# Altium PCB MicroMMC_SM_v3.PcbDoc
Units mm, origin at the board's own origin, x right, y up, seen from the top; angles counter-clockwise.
Board outline 50 x 25 mm, 4 copper layers (Top Layer, GND1, GND2, Bottom Layer), stack 1.586 mm thick; 71 components, 41 nets, 213 pads, 184 vias.
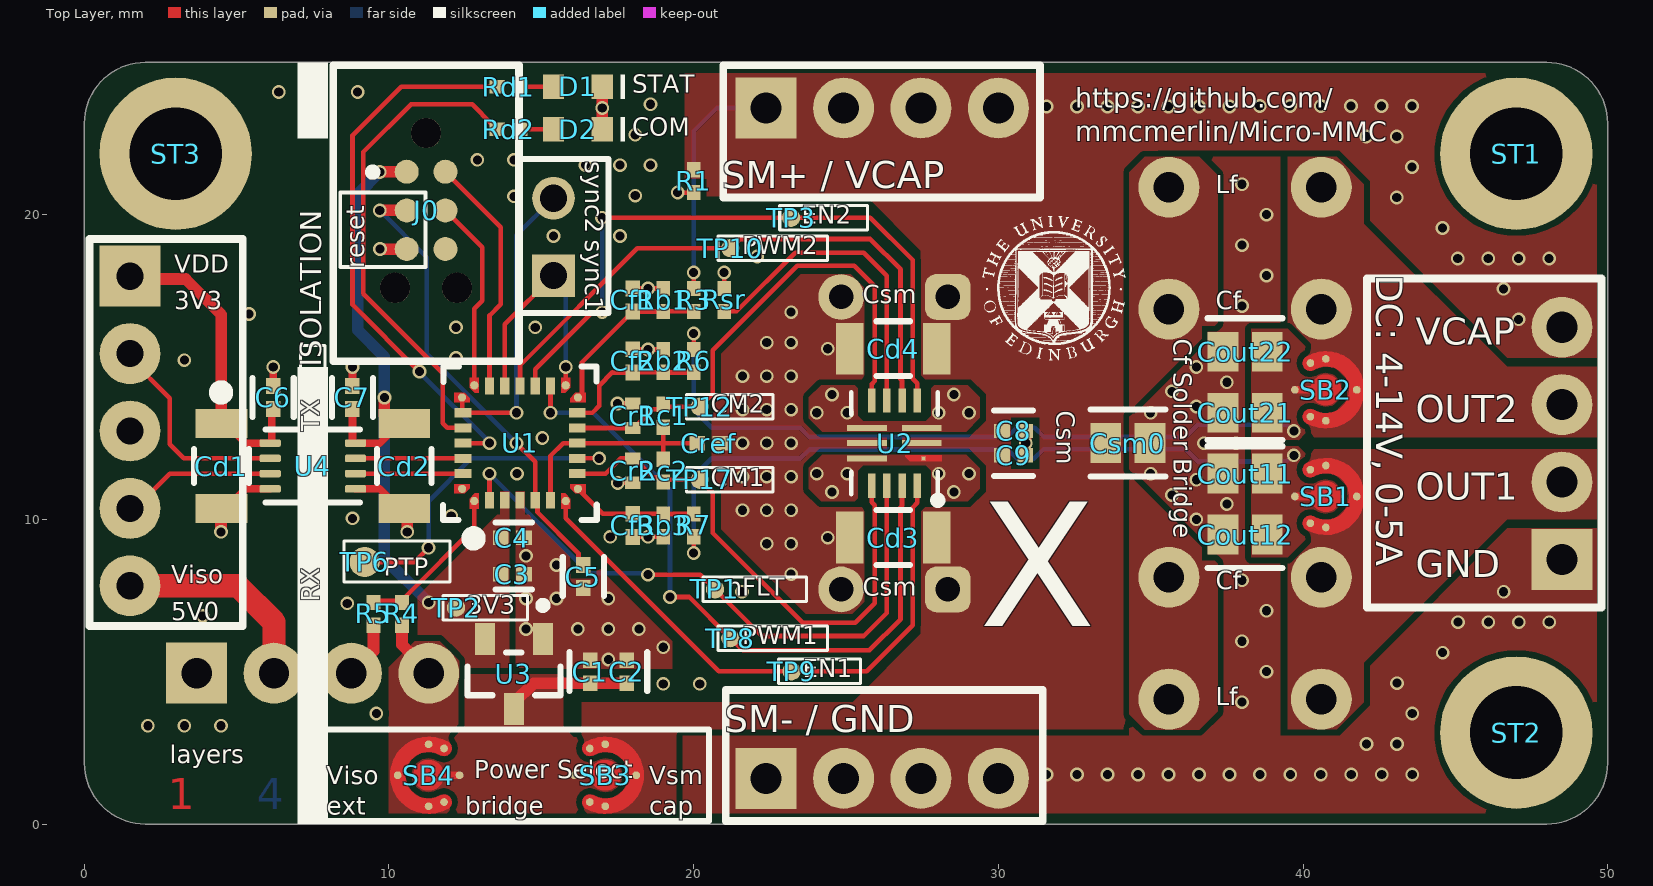
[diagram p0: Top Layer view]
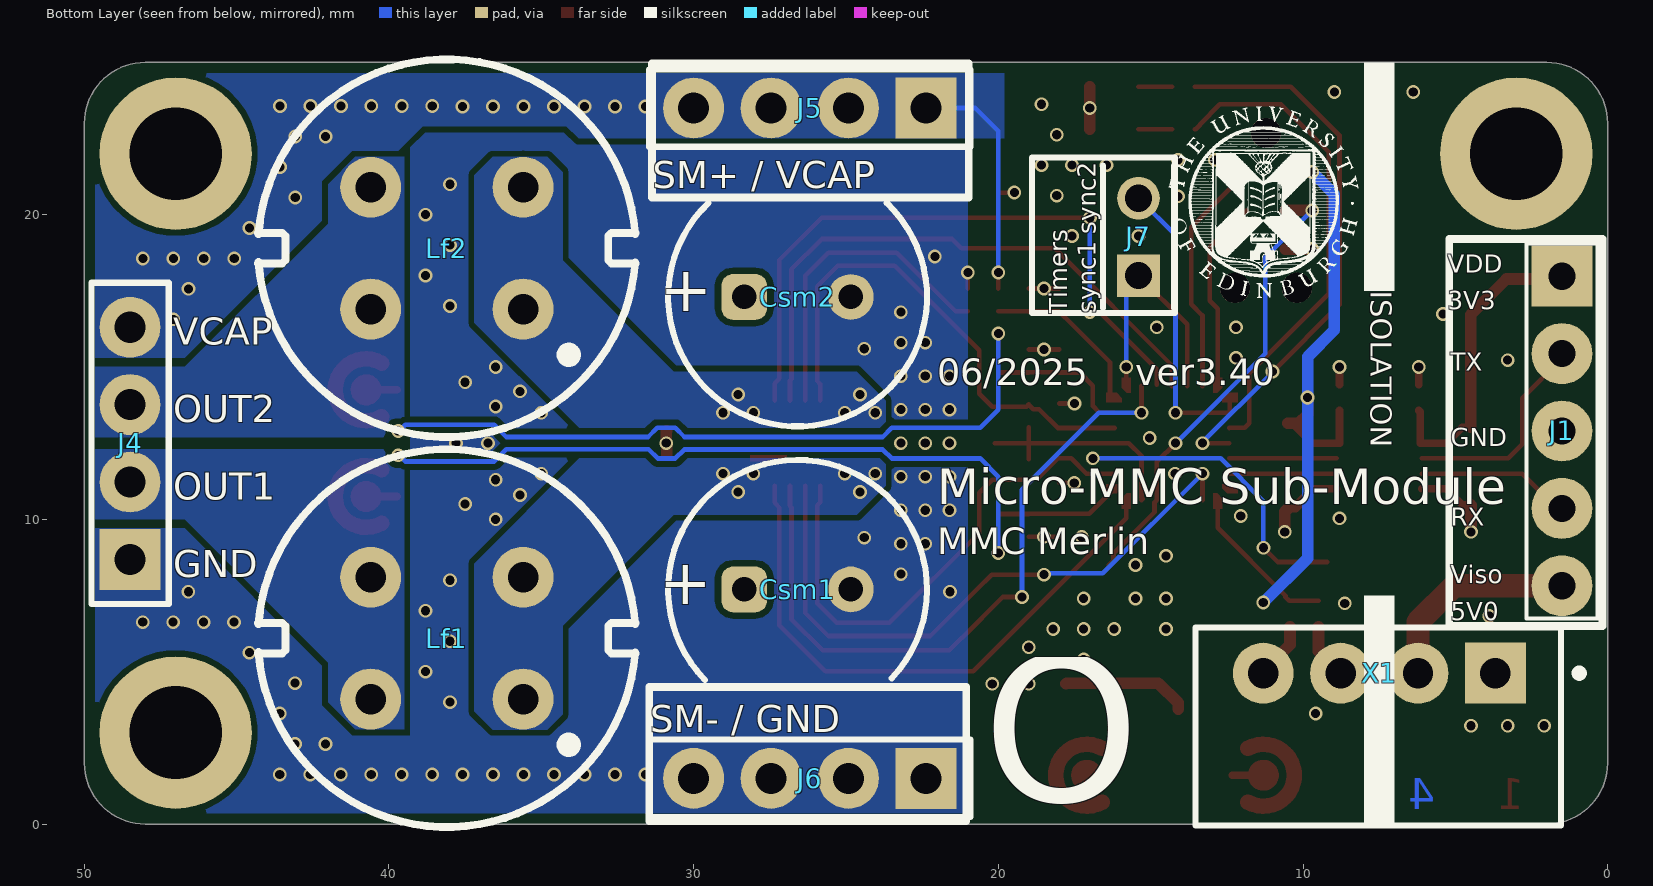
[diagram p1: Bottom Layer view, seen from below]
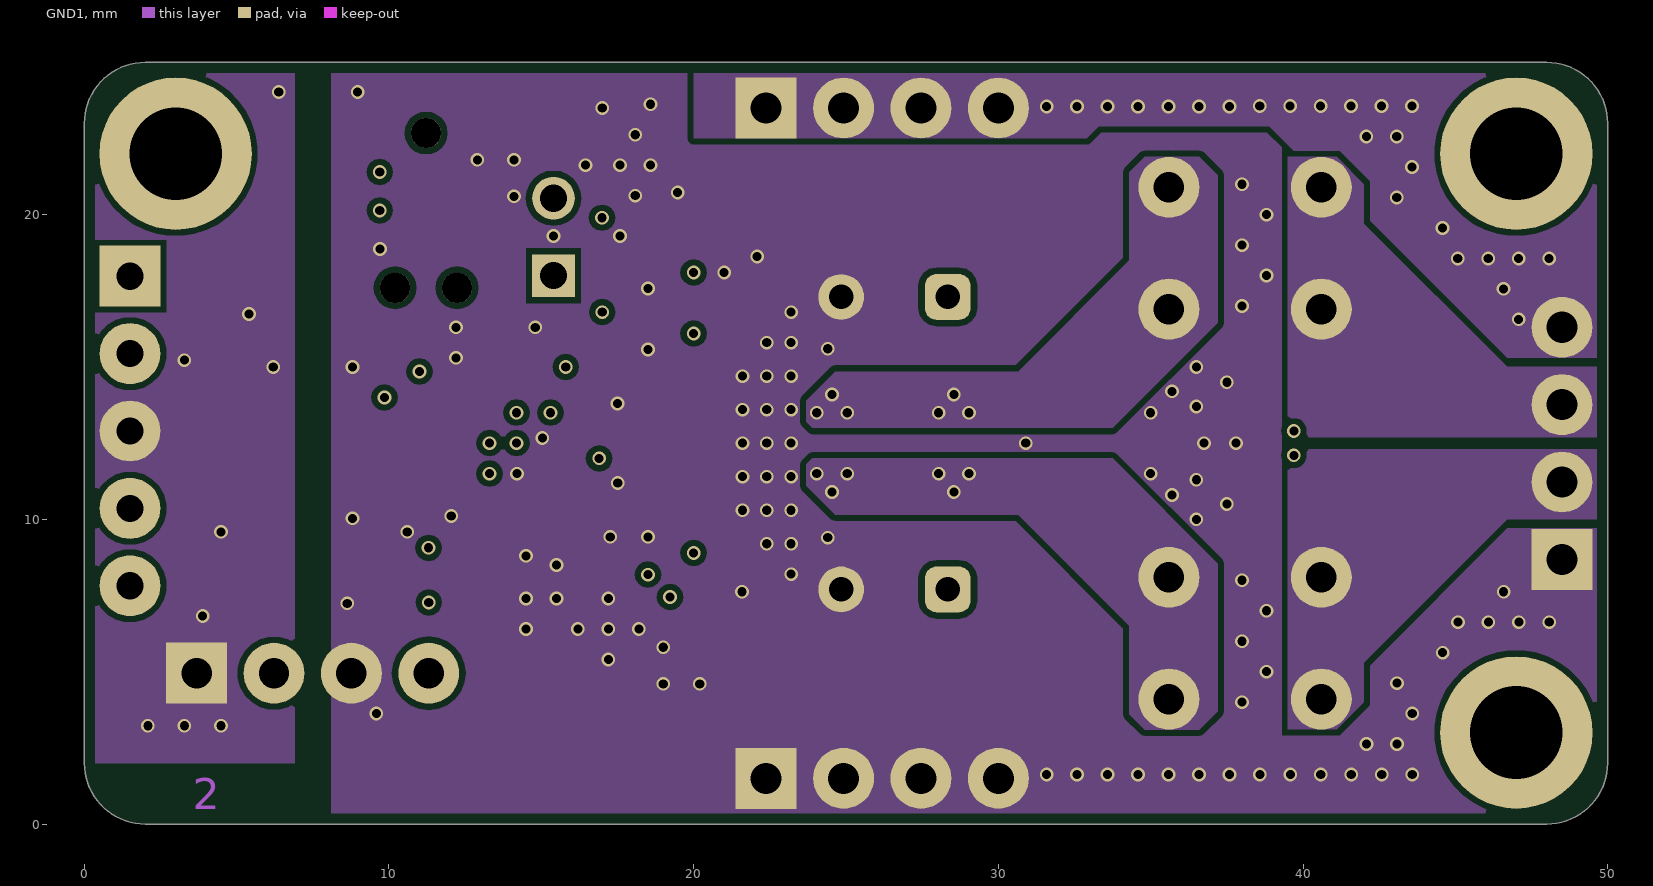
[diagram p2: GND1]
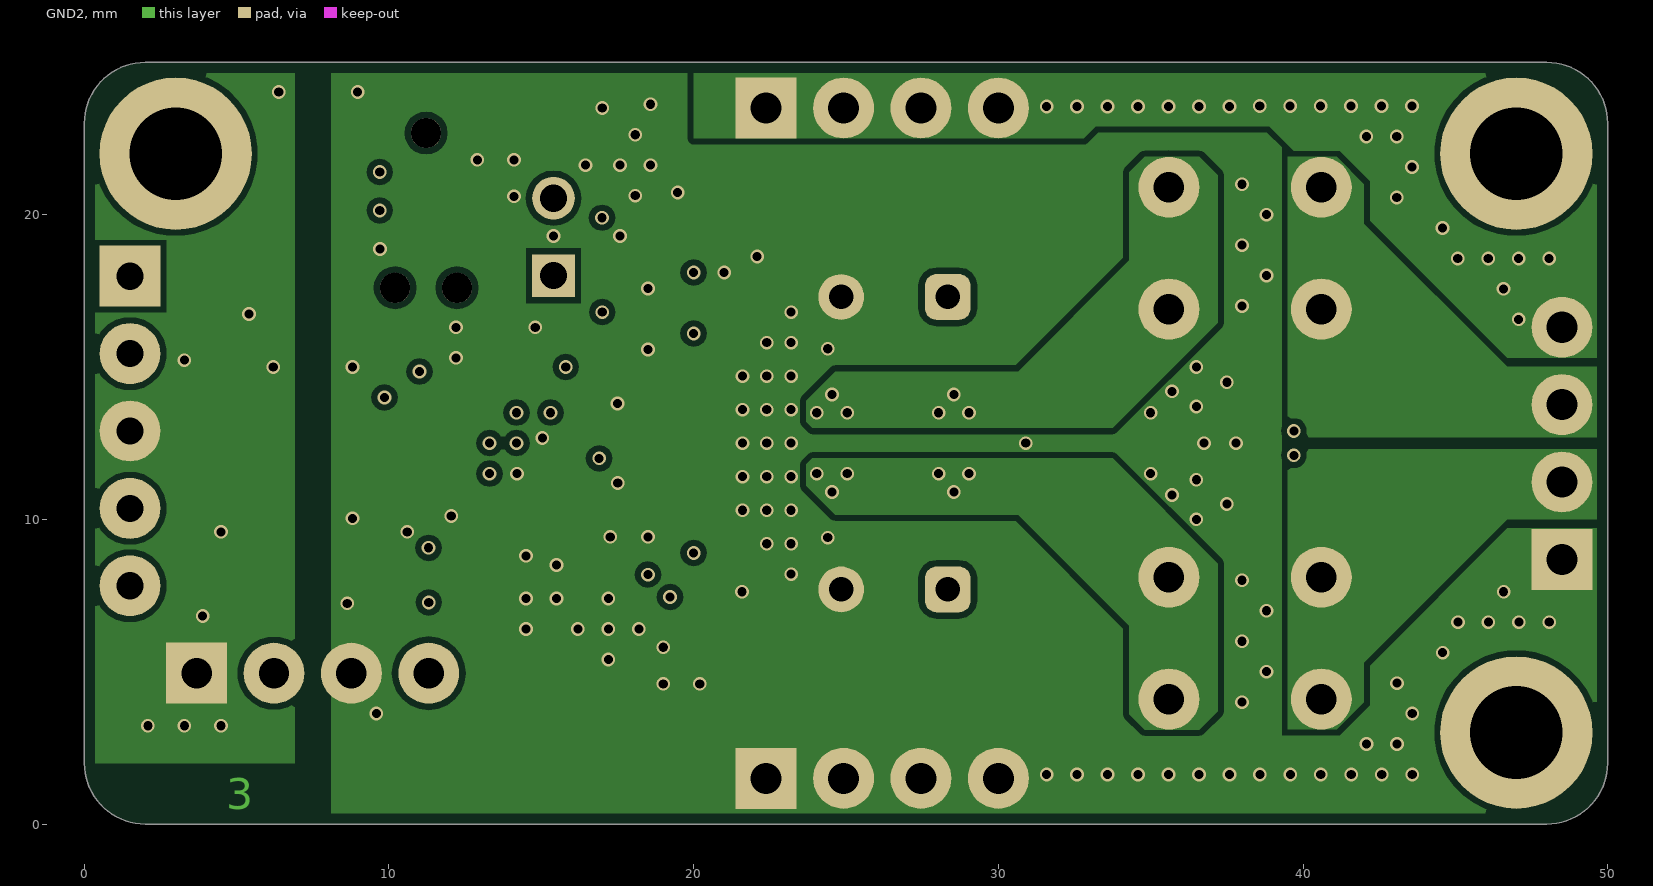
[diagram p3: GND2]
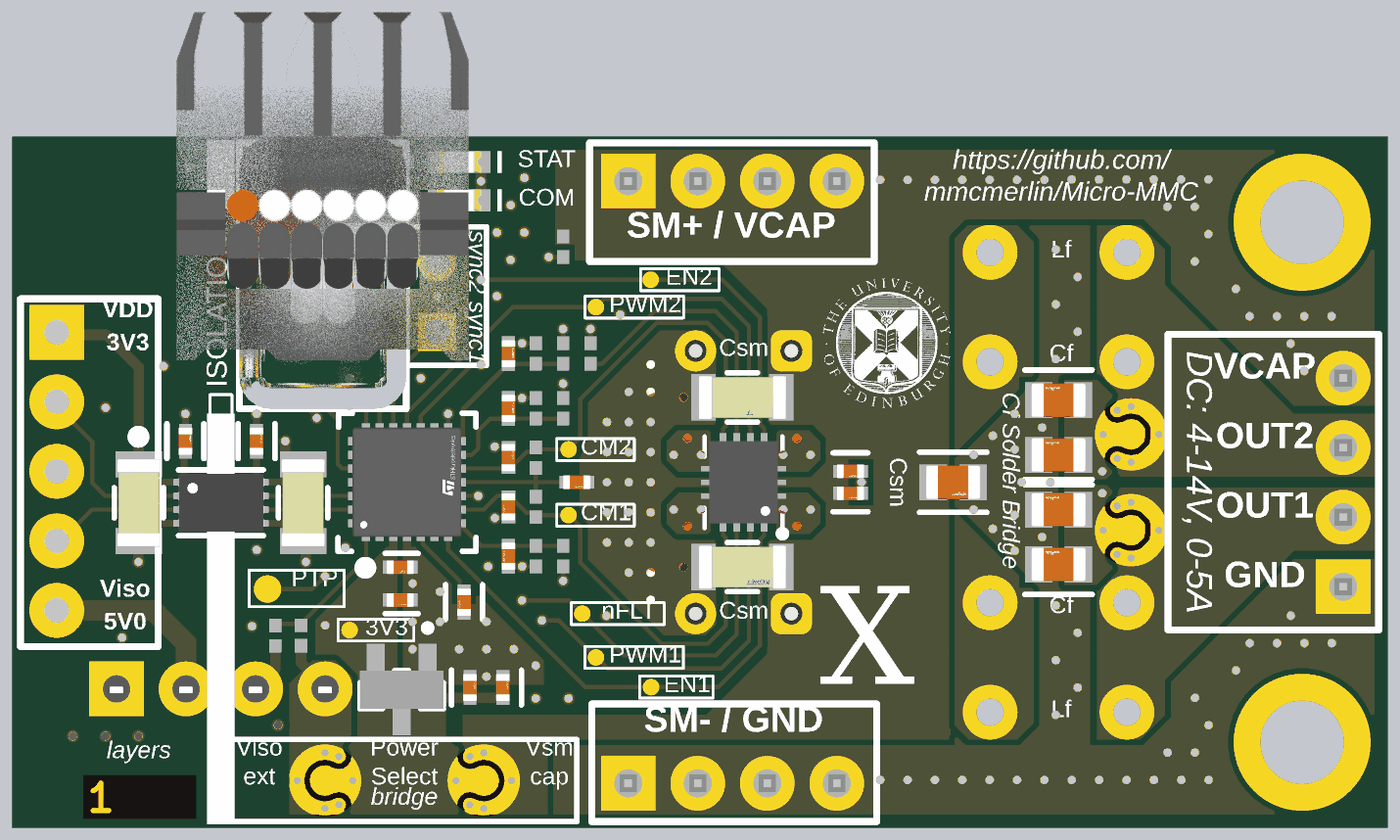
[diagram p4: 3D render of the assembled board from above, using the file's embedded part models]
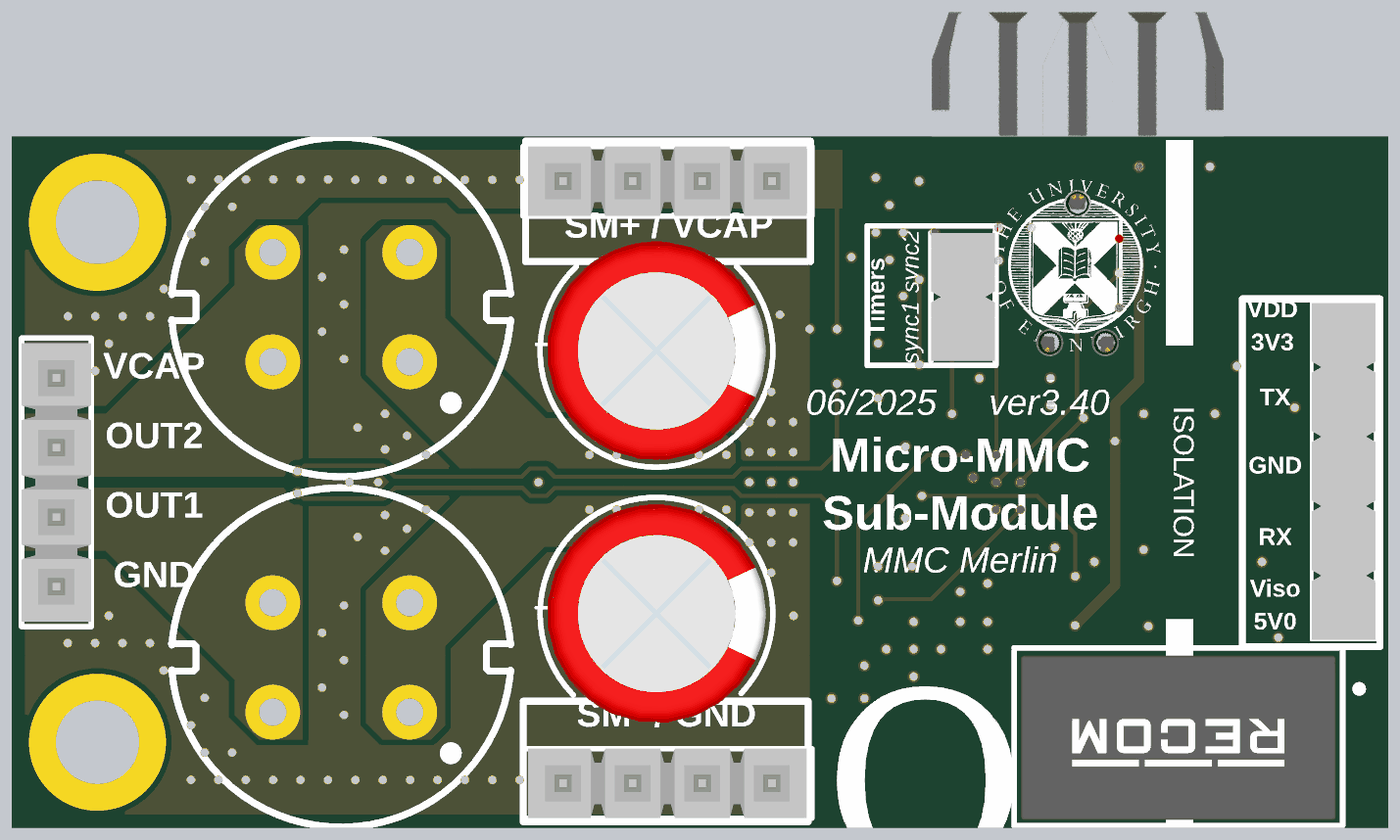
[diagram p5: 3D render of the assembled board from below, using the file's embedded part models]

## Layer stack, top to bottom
Top Solder: solder mask 0.0127, Solder Resist, Dk 3.8
Top Layer: signal copper 0.035
Dielectric 1: prepreg 0.2104, PP-022, Dk 4.6
GND1: signal copper 0.0152
Dielectric1: core 1.065, FR-4, Dk 4.6
GND2: signal copper 0.0152
Dielectric 2: prepreg 0.2104, PP-022, Dk 4.6
Bottom Layer: signal copper 0.035
Bottom Solder: solder mask 0.0127, Solder Resist, Dk 3.8

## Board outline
0,2 0,23 cw(c2,23) 2,25 48,25 cw(c48,23) 50,23 50,2 cw(c48,2) 48,0 2,0 cw(c2,2)

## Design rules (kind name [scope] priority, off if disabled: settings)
BoardOutlineClearance [All] p1: gap=0.35 ignorepadtopadclearanceinfootprint=FALSE
Clearance [All] p1: gap=0.2 ignorepadtopadclearanceinfootprint=FALSE except(0.254: Via-Via)
Height [All] p1: minheight=0 maxheight=100 prefheight=12.7
HoleSize [All] p1: absolutevalues=TRUE maxlimit=6 minlimit=0.25 maxpercent=80.000 minpercent=20.000
HoleToHoleClearance [All] p1: gap=0.45 allowstackedmicrovias=TRUE
MinimumSolderMaskSliver [All] p1: minsoldermaskwidth=0.1
PlaneConnect [All] p1: planeconnectstyle=Direct reliefexpansion=0.508 reliefentries=4 reliefconductorwidth=0.254 reliefairgap=0.254
PolygonConnect [All] p1: connectstyle=Direct reliefconductorwidth=0.254 reliefentries=4 polygonreliefangle="90 Angle" airgapwidth=0.254
RoutingVias [All] p1: holewidth=1 width=2 viastyle="Through Hole" minholewidth=0.3 minwidth=0.45 maxholewidth=6 maxwidth=12
SilkToSolderMaskClearance [IsPad] p1: minsilkscreentomaskgap=0.15 clearancetoexposedcopper=TRUE
SolderMaskExpansion [Not IsVia] p1: expansion=0.04 istentingtop=FALSE
SolderMaskExpansion SolderMaskExpansion_via [IsVia] p2: expansion=0.102 istentingtop=TRUE
SupplyNets "Schematic Supply Nets_5" [InNet('GND_SM')] p1: voltage=0.000
SupplyNets "Schematic Supply Nets_7" [InNet('Viso_SM')] p2: voltage=0.000
SupplyNets "Schematic Supply Nets_6" [InNet('+3.3V_SM')] p3: voltage=0.000
SupplyNets "Schematic Supply Nets_4" [InNet('Vdd_MA')] p4: voltage=0.000
SupplyNets "Schematic Supply Nets_3" [InNet('GND_MA')] p5: voltage=0.000
SupplyNets "Schematic Supply Nets_2" [InNet('V_REF')] p6: voltage=0.000
SupplyNets "Schematic Supply Nets_1" [InNet('Viso_MA')] p7: voltage=0.000
SupplyNets "Schematic Supply Nets" [InNet('VCAP_SM')] p8: voltage=0.000
UnRoutedNet [All] p1: checkbadconnections=TRUE
Width [All] p1: maxlimit=0.762 minlimit=0.152 preferedwidth=0.381
23 further rules are at their usual default settings.

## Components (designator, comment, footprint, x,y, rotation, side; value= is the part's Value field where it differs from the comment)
C1 "GRM155R61E105KA12D" FP-GRM155-0_05-IPC_C 16.6,5 r90 top
C2 "GRM155R61E105KA12D" FP-GRM155-0_05-IPC_C 17.8,5 r90 top
C3 "GRM155R61E105KA12D" FP-GRM155-0_05-IPC_C 14.05,8.2 r0 top
C4 "GRM155R61E105KA12D" FP-GRM155-0_05-IPC_C 14.05,9.4 r0 top
C5 "GRM155R61E105KA12D" FP-GRM155-0_05-IPC_C 16.379,8.121 r270 top
C6 "GRM155R61E105KA12D" FP-GRM155-0_05-IPC_C 6.2,14 r90 top
C7 "GRM155R61E105KA12D" FP-GRM155-0_05-IPC_C 8.8,14 r90 top
C8 "GRM155R61E105KA12D" FP-GRM155-0_05-IPC_C 30.5,12.9 r0 top
C9 "GRM155R61E105KA12D" FP-GRM155-0_05-IPC_C 30.5,12.1 r0 top
Cd1 "C1206C104M5RACTU" FP-C1206C-EB-MFG#1 4.5,11.75 r270 top value="0.10 μF"
Cd2 "C1206C104M5RACTU" FP-C1206C-EB-MFG#1 10.5,11.75 r270 top value="0.10 μF"
Cd3 "C1206C104M5RACTU" FP-C1206C-EB-MFG#2 26.55,9.4 r180 top value="0.10 μF"
Cd4 "C1206C104M5RACTU" FP-C1206C-EB-MFG#2 26.55,15.6 r180 top value="0.10 μF"
Cf1 "CL05B103KB5NNNC" FP-CL165-IPC_C 18,17.2 r90 top
Cf2 "CL05B103KB5NNNC" FP-CL165-IPC_C 18,15.2 r90 top
Cf3 "CL05B103KB5NNNC" FP-CL165-IPC_C 18,9.8 r270 top
Cout11 "GRM21BR61H475ME51L" FP-GRM21B-0_15-IPC_C 38.1,11.5 r180 top
Cout12 "GRM21BR61H475ME51L" FP-GRM21B-0_15-IPC_C 38.1,9.5 r180 top
Cout21 "GRM21BR61H475ME51L" FP-GRM21B-0_15-IPC_C 38.1,13.5 r180 top
Cout22 "GRM21BR61H475ME51L" FP-GRM21B-0_15-IPC_C 38.1,15.5 r180 top
Cr1 "GJM1555C1H100JB01D" FP-GJM155-0_05-MFG 18,13.4 r90 top
Cr2 "GJM1555C1H100JB01D" FP-GJM155-0_05-MFG 18,11.6 r270 top
Cref "GRM155R61E105KA12D" FP-GRM155-0_05-IPC_C 20.5,12.5 r0 top
Csm0 "GRM21BR61H475ME51L" FP-GRM21B-0_15-IPC_C 34.25,12.5 r0 top
Csm1 "860010474012" WCAP-ATG8_D8H11.5 26.59,7.7 r0 bottom value=470uF
Csm2 "860010474012" WCAP-ATG8_D8H11.5 26.59,17.3 r0 bottom value=470uF
D1 "150060RS75000" WL-SMCW_0603_150060xx75000 16.2,24.2 r180 top
D2 "150060RS75000" WL-SMCW_0603_150060xx75000 16.2,22.8 r180 top
J0 "TC2030-CTX-NL" FP-TC2030-CTX-NL-MFG 11.216,20.14 r270 top
J1 "5-146280-5" 5-146280-5 1.5,17.98 r270 bottom
J4 "TSW-104-08-L-S" SMTC-TSW-104-08-X-S 48.5,8.685 r90 bottom
J5 "TSW-104-08-L-S" SMTC-TSW-104-08-X-S 22.38,23.5 r0 bottom
J6 "TSW-104-08-L-S" SMTC-TSW-104-08-X-S 22.38,1.5 r0 bottom
J7 "5-146280-2" TECO-5-146280-2_V 15.4,19.27 r90 bottom
Lf1 "RCH1216BNP-100M" "TH Inductor" 35.6,8.1 r270 bottom
Lf2 "RCH1216BNP-100M" "TH Inductor" 35.6,20.9 r270 bottom
R1 "RC0402FR-0710KL" RESC1005X40X25LL05T10 20,21.1 r90 top
R3 "RC0402FR-0710KL" RESC1005X40X25LL05T10 20,17.2 r90 top
R4 "RC0402FR-0710KL" RESC1005X40X25LL05T10 10.426,6.897 r270 top
R5 "RC0402FR-0710KL" RESC1005X40X25LL05T10 9.491,6.896 r90 top
R6 "RC0402FR-0710KL" RESC1005X40X25LL05T10 20,15.2 r90 top
R7 "RC0402FR-0710KL" RESC1005X40X25LL05T10 20,9.8 r270 top
Rb1 "RC0402FR-073K3L" RESC1005X40X25LL05T10 19,17.2 r270 top
Rb2 "RC0402FR-073K3L" RESC1005X40X25LL05T10 19,15.2 r270 top
Rb3 "RC0402FR-073K3L" RESC1005X40X25LL05T10 19,9.8 r90 top
Rc1 "RC0402FR-073K3L" RESC1005X40X25LL05T10 19,13.4 r270 top
Rc2 "RC0402FR-073K3L" RESC1005X40X25LL05T10 19,11.6 r90 top
Rd1 "RC0402FR-073K3L" RESC1005X40X25LL05T10 13.925,24.2 r0 top
Rd2 "RC0402FR-073K3L" RESC1005X40X25LL05T10 13.925,22.8 r0 top
Rsr "RC0402FR-0710KL" RESC1005X40X25LL05T10 21,17.2 r270 top
SB1 "Solder-Bridge-NO" Solder-Bridge-NO-Footprint-1#1 40.75,10.75 r180 top
SB2 "Solder-Bridge-NO" Solder-Bridge-NO-Footprint-1#1 40.75,14.25 r180 top
SB3 "Solder-Bridge-NO" Solder-Bridge-NO-Footprint-1#2 17.1,1.6 r180 top
SB4 "Solder-Bridge-NO" Solder-Bridge-NO-Footprint-1#1 11.3,1.6 r0 top
ST1 "PTH-M3D0X5" PTH-M2D5X5#1 47,24.5 r0 top locked
ST2 "PTH-M3D0X5" PTH-M2D5X5#2 47,0.5 r0 top locked
ST3 "PTH-M3D0X5" PTH-M2D5X5#3 -7,24.5 r0 top locked
TP1 "TPAD6R" TP06R#1 20.7,7.7 r90 top
TP2 "TPAD6R" TP06R#1 12.2,7.1 r270 top
TP3 "TPAD6R" TP06R#1 23.2,19.9 r90 top
TP6 "TPAD6R" TP06R#2 9.2,8.6 r90 top locked
TP8 "TPAD6R" TP06R#1 21.2,6.1 r90 top
TP9 "TPAD6R" TP06R#1 23.214,5.014 r90 top
TP10 "TPAD6R" TP06R#1 21.2,18.9 r90 top
TP12 "TPAD6R" TP06R#1 20.2,13.7 r0 top
TP17 "TPAD6R" TP06R#1 20.2,11.3 r0 top
U1 "STM32G071GBU6" FP-UFQFPN28-A0B0-MFG 14.3,12.5 r90 top
U2 "MP6551GQB-P" QFN-14_MP6551_MNP 26.59,12.5 r180 top
U3 "MCP1799T-3302H/TT" FP-C04-104-MFG 14.1,4.925 r270 top
U4 "ISO6521REUR" SON50P300X105-8N 7.5,11.75 r0 top
X1 "RFM-0505S" FP-RFM-0505S-MFG 7.535,3.2 r0 bottom

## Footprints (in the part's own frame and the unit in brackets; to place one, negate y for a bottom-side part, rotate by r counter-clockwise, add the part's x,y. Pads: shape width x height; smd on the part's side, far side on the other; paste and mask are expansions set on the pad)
5-146280-5 [mm] "PCB Mount Header, Vertical, Board-to-Board, 5 Position, 2.54 mm [.1 in] Centerline, Breakaway, Gold (Au), Through Hole - Solder, AMPMODU Headers"
  rect 2x2 hole 0.89: 1(0,0)
  round 2 hole 0.89: 2(2.54,0) 3(5.08,0) 4(7.62,0) 5(10.16,0)
  silkscreen extent -1.07,-1.17 11.23,1.17, body extent -1.07,-1.17 11.23,1.17, height 8.19
FP-C04-104-MFG [mm]
  rect 1.05x0.65 smd paste+0 mask+0: 1(-1.15,0.95) 2(-1.15,-0.95) 3(1.15,0)
  silkscreen extent -2.37,-1.53 0.7,1.52, body extent -1.78,-1.88 1.78,1.87, height 0.25
FP-C1206C-EB-MFG#1 [mm]
  rect 0.95x1.7 smd paste+0 mask+0: 1(-1.4,0) 2(1.4,0)
  silkscreen extent -0.55,-0.9 0.55,0.9, body extent -2,-1 2,1, height 0.25
FP-C1206C-EB-MFG#2 [mm]
  rect 0.9x1.7 smd paste+0 mask+0: 1(-1.425,0) 2(1.425,0)
  silkscreen extent -0.55,-0.9 0.55,0.9, body extent -2,-1 2,1, height 0.25
FP-CL165-IPC_C [mm]
  rect 0.515x0.472 smd paste+0 mask+0: 1(-0.379,0) 2(0.379,0)
  body extent -0.74,-0.38 0.74,0.38, height 0.25
FP-GJM155-0_05-MFG [mm]
  rect 0.4x0.5 smd paste+0 mask+0: 1(-0.4,0) 2(0.4,0)
  body extent -0.7,-0.38 0.7,0.38, height 0.25
FP-GRM21B-0_15-IPC_C [mm]
  rect 1.006x1.308 smd paste+0 mask+0: 1(-0.726,0) 2(0.726,0)
  silkscreen extent -1.23,-1.1 1.23,-1.1, body extent -1.33,-0.8 1.33,0.8, height 0.25
FP-GRM155-0_05-IPC_C [mm]
  rect 0.515x0.472 smd paste+0 mask+0: 1(-0.379,0) 2(0.379,0)
  silkscreen extent -0.64,0.67 0.64,0.67, body extent -0.74,-0.38 0.74,0.38, height 0.25
FP-RFM-0505S-MFG [mm]
  rect 2x2 hole 1 paste-2539.97 mask+0: 1(-3.85,-1.75)
  round 2 hole 1 paste-2539.97 mask+0: 2(-1.31,-1.75) 3(1.23,-1.75) 4(3.77,-1.75)
  silkscreen extent -6.72,-3.25 6,3.25, body extent -5.75,-2.97 5.75,3.04, height 10.5
FP-TC2030-CTX-NL-MFG [mil]
  round 30.98 smd paste-39370.1 mask+0: 1(-50,-25) 2(-50,25) 3(0,-25) 4(0,25) 5(50,-25) 6(50,25)
  round 39.02 hole 39.02 unplated paste-99999 mask+0: ""(-100,0) ""(100,40) ""(100,-40)
  silkscreen extent -54,-74 -45,-64, body extent -199,-124 199,124, height 10
FP-UFQFPN28-A0B0-MFG [mm]
  round 0.27 smd paste+0 mask+0: 1(-1.9,1.5) 7(-1.9,-1.5) 8(-1.5,-1.9) 14(1.5,-1.9) 15(1.9,-1.5) 21(1.9,1.5) 22(1.5,1.9) 28(-1.5,1.9)
  rect 0.55x0.3 smd paste+0 mask+0: 2(-1.875,1) 3(-1.875,0.5) 4(-1.875,0) 5(-1.875,-0.5) 6(-1.875,-1) 16(1.875,-1) 17(1.875,-0.5) 18(1.875,0) 19(1.875,0.5) 20(1.875,1)
  rect 0.3x0.55 smd paste+0 mask+0: 9(-1,-1.875) 10(-0.5,-1.875) 11(0,-1.875) 12(0.5,-1.875) 13(1,-1.875) 23(1,1.875) 24(0.5,1.875) 25(0,1.875) 26(-0.5,1.875) 27(-1,1.875)
  Top Layer region: 1.65,1.35 1.65,1.48 1.82,1.65 2.15,1.65 2.15,1.35 1.65,1.35
  Top Layer region: -1.35,-1.65 -1.48,-1.65 -1.65,-1.82 -1.65,-2.15 -1.35,-2.15 -1.35,-1.65
  Top Layer region: -1.65,-1.35 -1.65,-1.48 -1.82,-1.65 -2.15,-1.65 -2.15,-1.35 -1.65,-1.35
  Top Layer region: 1.65,-1.35 1.65,-1.48 1.82,-1.65 2.15,-1.65 2.15,-1.35 1.65,-1.35
  Top Layer region: -1.65,1.35 -1.65,1.48 -1.82,1.65 -2.15,1.65 -2.15,1.35 -1.65,1.35
  Top Layer region: 1.35,-1.65 1.48,-1.65 1.65,-1.82 1.65,-2.15 1.35,-2.15 1.35,-1.65
  Top Layer region: 1.35,1.65 1.48,1.65 1.65,1.82 1.65,2.15 1.35,2.15 1.35,1.65
  Top Layer region: -1.35,1.65 -1.48,1.65 -1.65,1.82 -1.65,2.15 -1.35,2.15 -1.35,1.65
  silkscreen extent -3.32,-2.52 2.52,2.52, body extent -2.25,-2.25 2.25,2.25, height 0.25
PTH-M2D5X5#1 [mm]
  round 5 hole 3.05: 1(0,-2.5)
PTH-M2D5X5#2 [mm]
  round 5 hole 3.05: 1(0,2.5)
PTH-M2D5X5#3 [mm]
  round 5 hole 3.05: 1(10,-2.5)
QFN-14_MP6551_MNP [mm]
  rect 0.127x0.127 smd mask+0: 1(-0.95,0.5)
  rect 1.3x0.2 smd paste+0 mask+0: 2(-0.9,0) 3(-0.9,-0.5) 8(0.9,-0.5) 9(0.9,0) 10(0.9,0.5)
  rect 0.25x0.8 smd paste+0 mask+0: 4(-0.75,-1.4) 5(-0.25,-1.4) 6(0.25,-1.4) 7(0.75,-1.4) 11(0.75,1.4) 12(0.25,1.4) 13(-0.25,1.4) 14(-0.75,1.4)
  Top Layer region: -0.5,0.6 -1.55,0.6 -1.55,0.4 -0.35,0.4 -0.35,0.45
  silkscreen extent -1.42,-1.68 1.42,1.68, body extent -1.25,-1.5 1.25,1.5, height 0.87
RESC1005X40X25LL05T10 [mm] "Chip Resistor, 2-Leads, Body 1.00x0.50mm, IPC High Density"
  rect 0.5x0.45 smd: 1(-0.375,0) 2(0.375,0)
  body extent -0.53,-0.27 0.53,0.28, height 0.4
SMTC-TSW-104-08-X-S [mm] ".025 SQ Post Terminal Strip Assembly, 1x4 Pins, Vertical, 2.54mm Pitch, Male"
  rect 2x2 hole 1.02: 1(0,0)
  round 2 hole 1.02: 2(2.54,0) 3(5.08,0) 4(7.62,0)
  silkscreen extent -1.46,-1.27 9.08,1.27, body extent -1.27,-1.27 8.89,1.27, height 8.38
Solder-Bridge-NO-Footprint-1#1 [mil]
  round 10 smd mask+4: 1(-40,0) 1(0,40) 1(0,-40) 1(20,34.64) 1(20,-34.64)
  round 10 smd mask+0: 2(40,0)
  Top Layer circle w20: c0,0 r10
  Top Layer lines w10: 40,0 0,0
  Top Layer lines w20: 20,34.64 ccw(c0,0) 20,-34.64
Solder-Bridge-NO-Footprint-1#2 [mil]
  round 10 smd mask+4: 1(-40,0) 1(0,40) 1(0,-40) 1(20,34.64) 1(20,-34.64)
  round 10 smd mask+0: 2(40,0)
  Top Layer circle w20: c0,0 r10
  Top Layer lines w20: 20,34.64 ccw(c0,0) 20,-34.64
SON50P300X105-8N [mm] "SON, 8-Leads, Body 2.00x3.00mm, Pitch 0.50mm, IPC Medium Density"
  rrect50% 0.7x0.25 smd mask+0: 1(-1.4,0.75) 2(-1.4,0.25) 3(-1.4,-0.25) 4(-1.4,-0.75) 5(1.4,-0.75) 6(1.4,-0.25) 7(1.4,0.25) 8(1.4,0.75)
  silkscreen extent -3.21,-1.2 1.55,2.61, body extent -1.56,-1.05 1.56,1.05, height 1.05
TECO-5-146280-2_V [mm] "Connector, 2-Leads, Body 4.67x2.34mm, Pitch 2.54mm"
  rect 1.4x1.4 hole 0.89: 1(-1.27,0)
  round 1.4 hole 0.89: 2(1.27,0)
  silkscreen extent -2.33,-1.17 2.33,1.17, body extent -2.34,-1.17 2.34,1.17, height 5.33
"TH Inductor" [mm]
  round 2 hole 1: 1(4,0) 2(4,-5) 3(0,-5) 4(0,0)
  silkscreen extent -4.2,-8.7 8.2,3.7, body extent -4.27,-8.71 8.23,3.79, height 16.1
TP06R#1 [mm] "Testpoint, round, d=0.6mm"
  round 0.6 smd paste-1: 1(0,0)
TP06R#2 [mm] "Testpoint, round, d=0.6mm"
  round 1 smd paste-1: 1(0,0)
WCAP-ATG8_D8H11.5 [mm] "Aluminum Electrolytic Capacitors, 8x11.5mm"
  rrect50% 1.5x1.5 hole 0.8: 1(1.75,0)
  round 1.5 hole 0.8: 2(-1.75,0)
  silkscreen extent -4.25,-4.25 4.25,2.97, body extent -3.99,-4 3.99,3.99, height 11.81
WL-SMCW_0603_150060xx75000 [mm] "SMD Mono-color Chip LED, body 1.60 x 0.80 mm"
  rect 0.7x0.8 smd: 1(-0.8,0) 2(0.8,0)
  silkscreen extent -1.55,-0.4 -1.4,0.4, body extent -0.8,-0.4 0.8,0.4, height 0.7

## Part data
C1 C2 C3 C4 C5 C6 C7 C8 C9 Cref: library part CMP-2008-04581-2, "Chip Multilayer Ceramic Capacitors for General Purpose, 0402, 1.0uF, X5R, 15%, 10%, 25V", Capacitance=1uF, Case Code (Imperial)=0402, Case Code (Metric)=1005, Dielectric=X5R, JLCPCB Part #=C52923, Max Operating Temperature=85°C, Min Operating Temperature=-55°C, Package Quantity=10000, Tolerance=10%, Voltage=25V
Cd1 Cd2 Cd3 Cd4: library part CMP-03020-028488-1, "CAP CER 0.1UF 50V X7R 1206", Capacitance="0.10 μF", JLCPCB Part #=C24497, Manufacturer=KEMET, Package=C1206C-EB, Temperature="-55°C to +150°C", Temperature Characteristic=X7R, Temperature Coefficient=15%, Temperature Range High=+150°C, Temperature Range Low=-55°C, Tolerance=0.2, Voltage Rating="50 V"
Cf1 Cf2 Cf3: library part CMP-13271-000387-1, "Cap Ceramic 10nF 50V X7R ±10% SMD 0402 +125°C Paper T/R", Capacitance=10nF, Case Code (Imperial)=0402, Case Code (Metric)=1005, Dielectric=X7R, JLCPCB Part #=C15195, Max Operating Temperature=125°C, Min Operating Temperature=-55°C, Package Quantity=1, Tolerance=10%, Voltage=50V
Cout11 Cout12 Cout21 Cout22 Csm0: library part CMP-06035-037765-1, "Chip Multilayer Ceramic Capacitors for General Purpose, 0805, 4.7uF, X5R, 15%, 20%, 50V", Capacitance=4.7uF, Case Code (Imperial)=0805, Case Code (Metric)=2012, Dielectric=X5R, JLCPCB Part #=C98192, Max Operating Temperature=85°C, Min Operating Temperature=-55°C, Package Quantity=3000, Resistor Type=Ceramic, Tolerance=20%, Voltage Rating=50V
Cr1 Cr2: library part CMP-2008-03797-2, "Multi-Layer Ceramic Capacitor 10pF C0G  ±5% 0402 Paper T/R", Capacitance=10pF, Case Code (Imperial)=0402, Case Code (Metric)=1005, Dielectric=C0G, JLCPCB Part #=C32949, Max Operating Temperature=125°C, Min Operating Temperature=-55°C, Package Quantity=1, Tolerance=5%, Voltage=50V
Csm1 Csm2: library part CMP-03913-54007214-1, "860010474012 WCAP-ATG8 Aluminum Electrolytic Capacitors", Capacitance=330µF, Capacitor Type=Aluminium, Case/Package=Radial, Leakage Current=82.5µA, Manufacturer=Panasonic, Manufacturer Part Number=ECA-1CHG471, Max Operating Temperature=85°C, Min Operating Temperature=-40°C, Package Shape=Cylindrical, Package Style=RadialMeter, Rated DC Voltage (URdc)=16V, Ripple Current=451mA, Supplier Part Number 1=667-ECA-1CHG471, Tolerance=20%, Voltage Rating=25V
D1 D2: library part CMP-1426-00001-4, "LED Low-Power Uni-Color Red 630nm 2V 2-Pin Chip 0603(1608Metric) T/R", Case Code (Imperial)=0603, Case Code (Metric)=1608, Color=Red, Forward Current=100mA, Forward Voltage=2V, JLCPCB Part #=C2286, Max Junction Temperature (Tj)=95°C, Max Operating Temperature=85°C, Max Reverse Voltage (DC)=5V, Min Operating Temperature=-40°C, Power Dissipation=72mW, Test Current=20mA
J0: library part CMP-205963-000001-1, "6-Pin “No legs” TC2030 Plug-of-Nails™ Cable for use with ARM Cortex processors"
J1: library part CMP-002-00297-1, "Board Connector, 5 Contact(s), 1 Row(s), Male, Straight, Solder Terminal"
J4 J5 J6: library part CMP-1024-00358-1, "0.025\" SQ Post Header, Through-hole, Vertical, -55 to 125 degC, 2.54 mm Pitch, 4-Pin, Male, RoHS", Flammability Rating="UL94 V-0", Manufacturer=Samtec, Manufacturer Part Number=G800W304018EU, Supplier Part Number 1=3882398, Temperature Range="-55 to 125 degC"
J7: library part CMP-2000-07492-1, "Male Header, Pitch 2.54 mm, 1 x 2 Position, Height 8.21 mm, Tail Length 3.05 mm, -65 to 105 degC, RoHS, Bulk", Case\/Package=100, Colour=Black, Current Rating=3A, Flammability Rating=UL94V-0, High Temperature Housing=Yes, Manufacturer="TE Connectivity", Max Current Rating=5A, Max Operating Temperature=105degC, Min Operating Temperature=-65degC, Package Description="Male Header, Pitch 2.54 mm, 1 x 2 Position, Height 8.21 mm, Tail Length 3.05 mm", Package Quantity=500
Lf1 Lf2: library part CMP-006-00026-4, "Ind Power Unshielded Wirewound 10uH 20% 1KHz Ferrite 5A Pin Box"
R1 R3 R4 R5 R6 R7 Rsr: library part CMP-2002-07353-1, JLCPCB Part #=C25744, Manufacturer="Yageo / Phycomp", Resistance=10kΩ
Rb1 Rb2 Rb3 Rc1 Rc2 Rd1 Rd2: library part CMP-2002-07652-1, "3.3k", JLCPCB Part #=C25890, Manufacturer="Yageo / Phycomp", Resistance=3.3kΩ
SB1 SB2 SB3 SB4: library part CMP-00030-00003-3, "Normally Open Solder Bridge 10mil gap"
ST1 ST2 ST3: library part CMP-00028-00004-1, "M3.0 PTH (3.0mm), 5mm pad"
TP1 TP2 TP3 TP6 TP8 TP9 TP10 TP12 TP17: library part CMP-00028-00002-1, "0.6mm round"
U1: library part CMP-12105-000098-1, "IC MCU 32BIT 128KB FLSH 28UFQFPN", Case/Package=UFQFPN, Frequency=64MHz, JLCPCB Part #=C529347, Max Operating Temperature=85°C, Min Operating Temperature=-40°C
U2: library part CMP-024-00000-3, "Brushed DC Motor Driver Dual Half-Bridge PWM 2.5V to 14V 5A 14-Pin QFN", JLCPCB Part #=C3681210
U3: library part CMP-06324-000112-1, "IC REG LINEAR 3.3V 80MA SOT23-3", JLCPCB Part #=C7424770
U4: library part CMP-015-00010-3, "Functional isolation dual-channel 1/1 digital isolator 8-VSON -40 to 125", JLCPCB Part #=C22428095
X1: library part CMP-29842-000017-1, "DC DC CONVERTER 5V 1W", Max Output Voltage=5V

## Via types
v1: diameter 0.45, hole 0.3, Top Layer to Bottom Layer, tented both sides, 184 vias

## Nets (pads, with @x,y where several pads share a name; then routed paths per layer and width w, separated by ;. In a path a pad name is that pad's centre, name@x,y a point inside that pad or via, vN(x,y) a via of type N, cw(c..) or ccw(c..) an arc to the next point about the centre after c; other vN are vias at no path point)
+3.3V_SM: C3.1 C4.1 C7.1 Cd2.1 J0.1 TP2.1 U1.3 U3.2 U4.8 | length 20.3
  Top Layer w0.254: C7.1@8.8,13.571 8.802,13.571 8.802,12.502 8.804,12.5 U4.8 9.697,12.5 Cd2.1@10.224,13.026
  Top Layer w0.381: v1(9.697,21.4) 9.702,21.405 10.576,21.405 J0.1 ; v1(9.85,14) 9.85,13.434 10.135,13.15 Cd2.1
  Bottom Layer w0.381: v1(9.697,21.4) 8.971,20.673 8.971,16.214 9.85,15.334 v1(9.85,14) 9.85,8.727 v1(11.305,7.272)
Cf1: Cout11.1 Cout12.1 R7.2 SB1.2 | length 23.6
  Top Layer w0.152: v1(20,8.897) R7.2
  Bottom Layer w0.152: v1@20,8.9 20,11.4 20.599,11.999 23.5,11.999 23.791,12.29 30.309,12.29 30.6,11.999 31.181,11.999 31.483,12.3 36.149,12.3 36.549,11.9 39.462,11.9 39.662,12.1 v1(39.7,12.1)
Cf2: Cout21.1 Cout22.1 R6.2 SB2.2 | length 23.6
  Top Layer w0.152: R6.2 v1(20,16.1)
  Bottom Layer w0.152: v1(20,16.1) 20,13.6 20.599,13.001 23.5,13.001 23.8,12.701 ; 23.8,12.7 30.3,12.7 ; 30.3,12.701 30.6,13.001 31.2,13.001 31.5,12.701 36.15,12.701 36.549,13.1 39.462,13.1 39.662,12.9 v1(39.7,12.9)
EN1: TP9.1 U1.7 U2.14 | length 19.3
  Top Layer w0.152: U1.7 15.8,10.033 20.818,5.014 TP9.1 25.679,5.014 27.189,6.524 27.189,10.389 27.34,10.54 U2.14
EN2: TP3.1 U1.17 U2.4 | length 22
  Top Layer w0.152: U1.17@14.801,14.416 14.801,14.922 16.671,16.793 16.993,16.793 v1(17,16.8) ; v1(16.993,19.9) 25.8,19.9 27.189,18.511 27.189,14.611 27.34,14.46 U2.4
  Bottom Layer w0.152: v1(17,16.8) v1@17,19.893
GND_MA: C6.2 Cd1.2 J1.3 U4.4 X1.1 | length 3.3
  Top Layer w0.254: Cd1.2@4.5,10.474 4.776,10.474 5.303,11 U4.4 ; C6.2@6.2,14.429 v1(6.2,15)
  Top Layer w0.381: v1(4.484,9.589) 4.484,10.458 Cd1.2@4.5,10.474
  other v1: 2.084,3.224 3.284,3.224 4.484,3.224 3.884,6.824 3.284,15.224 5.403,16.743 6.383,24.029
GND_SM: C1.2 C2.2 C3.2 C4.2 C5.2 C7.2 C8.2 C9.2 Cd2.2 Cd3.2 Cd4.2 Cf1.2 Cf2.2 Cf3.2 Cout11.2 Cout12.2 Cout21.2 Cout22.2 Cr1.2 Cr2.2 Cref.2 Csm0.2 Csm1.2 Csm2.2 D1.1 D2.1 J0.5 J4.1 J6.1 J6.2 J6.3 J6.4 R1.1 R5.1 Rb1.1 Rb2.1 Rb3.1 Rsr.1 U1.4 U2.9 U3.1 U4.5 X1.3 | length 13.6
  Top Layer w0.152: v1(17.5,13.8) Cr1.2 ; v1(17.508,11.192) 17.511,11.196 17.996,11.196 Cr2.2 ; Cf2.2 18.004,15.575 Rb2.1 ; Cf1.2 18.004,17.575 Rb1.1 ; Cf3.2@18.004,9.425 Rb3.1 ; v1(19.475,20.725) R1.1 ; Rsr.1 v1(21,18.1)
  Top Layer w0.254: C7.2@8.8,14.429 v1(8.8,15) ; U4.5 9.697,11 Cd2.2@10.224,10.474 ; Cd2.2@9.9,10.698 10.248,10.35 Cd2.2
  Top Layer w0.381: X1.3 9.491,5.676 R5.1@9.491,6.471 ; v1(9.702,18.87) J0.5 ; Cd2.2 10.6,10.25 v1(10.6,9.589) ; D2.1 v1(17,23.5) D1.1 ; C9.2 30.889,12.1 30.889,12.489 v1(30.9,12.5) ; C8.2 30.9,12.879 v1@30.9,12.542
  other v1: 31.584,1.624 32.584,1.624 33.584,1.624 34.585,1.624 35.585,1.624 36.585,1.624 37.585,1.624 38.585,1.624 39.585,1.624 40.585,1.624 41.585,1.624 42.585,1.624 43.585,1.624 42.085,2.624 43.085,2.624 9.584,3.624 43.585,3.624 38,4 19,4.6 20.2,4.6 43.085,4.624 38.8,5 17.2,5.4 44.585,5.624 19,5.8 38,6 14.5,6.4 16.2,6.4 17.2,6.4 18.2,6.4 45.085,6.624 46.085,6.624 47.085,6.624 48.085,6.624 38.8,7 8.631,7.241 14.5,7.4 15.5,7.4 17.2,7.4 21.584,7.624 46.585,7.624 38,8 23.2,8.2 15.5,8.5 14.5,8.8 22.4,9.2 23.2,9.2 24.4,9.4 17.262,9.425 18.502,9.425 36.5,10 8.804,10.033 12.042,10.109 21.6,10.3 22.4,10.3 23.2,10.3 37.5,10.5 35.7,10.8 36.5,11.3 21.6,11.4 22.4,11.4 23.2,11.4 14.2,11.499 35,11.5 21.6,12.5 22.4,12.5 23.2,12.5 36.75,12.5 37.8,12.5 15.032,12.671 35,13.5 21.6,13.6 22.4,13.6 23.2,13.6 36.5,13.7 35.7,14.2 37.5,14.5 21.6,14.7 22.4,14.7 23.2,14.7 36.5,15 12.2,15.3 18.5,15.575 24.4,15.6 22.4,15.8 23.2,15.8 12.2,16.3 14.801,16.3 23.2,16.8 38,17 18.5,17.575 38.8,18 22.084,18.624 38,19 15.4,19.3 17.584,19.3 38.8,20 14.1,20.6 18.084,20.624 38,21 16.45,21.624 17.584,21.624 18.584,21.624 12.9,21.8 14.1,21.8 18.084,22.624 18.584,23.624 8.971,24.029
HB_nFAULT: TP1.1 U1.2 U2.12 | length 20.6
  Top Layer w0.152: U1.2 v1(13.299,11.499) ; v1(18.499,8.185) 20.215,8.185 TP1.1 22.23,6.17 25.583,6.17 26.34,6.926 U2.12
  Bottom Layer w0.152: v1(13.299,11.499) 16.573,8.225 18.459,8.225 v1(18.499,8.185)
LED_COM: Rd2.1 U1.24 | length 16.1
  Top Layer w0.152: U1.24 11.918,13 11.768,13.15 11.768,14.791 9.156,17.402 9.156,22.056 10.724,23.624 12.726,23.624 13.376,22.974 13.376,22.949 13.525,22.8 Rd2.1
led_com_r: D2.2 Rd2.2 | length 1.1
  Top Layer w0.152: Rd2.2 D2.2
led_stat_r: D1.2 Rd1.2 | length 1.1
  Top Layer w0.152: Rd1.2 D1.2
LED_STATUS: Rd1.1 U1.25 | length 18.2
  Top Layer w0.152: v1(11,14.85) 8.804,17.046 8.804,22.607 10.397,24.2 Rd1.1 ; U1.25@12.426,12.501 v1(13.3,12.501)
  Bottom Layer w0.152: v1(11,14.85) 11,14.826 13.3,12.526 v1(13.3,12.501)
nRESET: C5.1 J0.3 U1.5 | length 15.3
  Top Layer w0.152: v1@14.183,12.5 14.8,11.883 U1.5 14.874,10.551 14.874,10.337 14.874,10.236 16.219,8.891 16.219,8.66 C5.1
  Top Layer w0.381: v1(9.697,20.14) J0.3
  Bottom Layer w0.152: v1(9.697,20.14) 11.242,18.595 11.242,15.442 v1(14.183,12.501)
OUT1_1: Lf1.1 Lf1.4 U2.1 U2.10
  other v1: 24.54,10.9 28.54,10.9 24.04,11.5 25.04,11.5 28.04,11.5 29.04,11.5
OUT1_2: J4.2 Lf1.2 Lf1.3 SB1.1
OUT2_1: Lf2.1 Lf2.4 U2.3 U2.8
  other v1: 24.04,13.5 25.04,13.5 28.04,13.5 29.04,13.5 24.54,14.1 28.54,14.1
OUT2_2: J4.3 Lf2.2 Lf2.3 SB2.1
ProgTP: TP6.1 U1.10 | length 10.7
  Top Layer w0.152: TP6.1 10.835,8.6 v1(11.3,9.065) ; U1.10@16.176,12.001 v1@16.898,12.001
  Bottom Layer w0.152: v1(11.3,9.065) 11.3,10.6 12.7,12 16.898,12 v1(16.899,12.001)
PWM1: TP8.1 U1.16 U2.13 | length 22.5
  Top Layer w0.152: v1(15.3,13.5) U1.16 ; v1(19.225,7.45) 19.85,7.45 TP8.1 21.207,6.107 21.613,5.7 25.769,5.7 26.79,6.721 26.79,10.395 26.84,10.445 U2.13
  Bottom Layer w0.152: v1(15.3,13.5) 16.7,13.5 19.225,10.975 v1(19.225,7.45)
PWM2: TP10.1 U1.18 U2.5 | length 19.6
  Top Layer w0.152: U1.18 14.3,15.05 18.15,18.9 TP10.1 ; TP10.1@21.213,18.9 21.513,19.2 25.8,19.2 26.79,18.21 26.79,14.605 26.84,14.555 U2.5
RX_MA: J1.2 U4.2 | length 7
  Top Layer w0.152: J1.2 1.5,15.28 2.8,13.98 2.8,12.469 3.269,12 U4.2
RX_SM: U1.27 U4.6 | length 3.5
  Top Layer w0.152: U4.6 U1.27
SR: Rsr.2 U2.6 | length 10.5
  Top Layer w0.152: Rsr.2 21.405,16.825 23.334,18.754 25.58,18.754 26.34,17.994 U2.6
SWCLK: J0.4 U1.21 | length 6.3
  Top Layer w0.152: J0.4 13.06,18.931 13.06,17.175 12.8,16.915 U1.21
SWDIO: J0.2 U1.20 | length 8
  Top Layer w0.152: J0.2 13.671,19.59 13.671,17.061 13.3,16.69 13.3,14.495 13.24,14.435 U1.20
TIM1_SYNC: J7.1 U1.15 U1.19 | length 8.1
  Top Layer w0.152: U1.19 13.8,16.4 J7.1 ; U1.15 v1(15.8,15)
  Bottom Layer w0.152: J7.1 15.8,17.6 v1(15.8,15)
TIM2_SYNC: J7.2 U1.22 U1.23 | length 9.8
  Top Layer w0.152: U1.22 12.4,13.525 U1.23 ; U1.23 v1(14.183,13.5)
  Bottom Layer w0.152: v1(14.183,13.5) 14.183,19.323 J7.2
TX_MA: J1.4 U4.3 | length 5.1
  Top Layer w0.152: J1.4 1.66,10.36 2.8,11.5 U4.3
TX_SM: U1.26 U4.7 | length 3.5
  Top Layer w0.152: U4.7 U1.26
V_CM1: Cr2.1 Rc2.1 TP17.1 U1.9 U2.11 | length 17.2
  Top Layer w0.152: U1.9 17.106,11.5 17.606,12 18.05,12 18.666,11.384 18.851,11.384 19,11.235 Rc2.1 19.075,11.3 TP17.1 20.624,10.876 20.624,9.551 23.575,6.6 25.3,6.6 25.941,7.241 25.941,10.459 25.84,10.56 U2.11
V_CM2: Cr1.1 Rc1.1 TP12.1 U1.12 U2.7 | length 16.9
  Top Layer w0.152: U1.12 17.2,13 18.05,13 18.666,13.616 18.851,13.616 19,13.765 Rc1.1 19.075,13.7 TP12.1 20.624,14.124 20.624,15.545 23.405,18.326 25.265,18.326 25.941,17.65 25.941,14.541 25.84,14.44 U2.7
V_iso: R4.1 R5.2 U1.1 | length 5.2
  Top Layer w0.152: R5.2@9.492,7.322 10.451,7.322 10.574,7.446 10.574,7.496 12.8,9.722 U1.1
V_out1: Cf3.1 R7.1 Rb3.2 U1.8 | length 4.1
  Top Layer w0.152: U1.8 17.021,10.179 Cf3.1 Rb3.2@19,10.179 ; Rb3.2 R7.1
V_out2: Cf2.1 R6.1 Rb2.2 U1.13 | length 4.8
  Top Layer w0.152: U1.13 16.679,13.5 16.9,13.721 16.9,14.39 17.332,14.821 Cf2.1 18.004,14.825 Rb2.2 19.004,14.821 19.996,14.821 R6.1
V_REF: Cref.1 Rc1.2 Rc2.2 U1.6 U1.11 | length 7.5
  Top Layer w0.152: U1.6 15.256,10.669 15.3,10.712 15.3,12.086 15.714,12.5 U1.11 16.689,12.5 16.691,12.502 18.291,12.502 18.293,12.5 19,12.5 ; Rc2.2 19,12.5 ; Rc1.2 19,12.5 ; Cref.1 20.1,12.5 19.975,12.5 19,12.5
V_sm: Cf1.1 R3.1 Rb1.2 U1.14 | length 5.6
  Top Layer w0.152: U1.14 16.222,14.023 16.316,14.023 16.335,14.041 16.335,15.157 17.817,16.64 17.84,16.64 18,16.8 Cf1.1 18.996,16.821 Rb1.2 R3.1
VCAP_SM: C8.1 C9.1 Cd3.1 Cd4.1 Csm0.1 Csm1.1 Csm2.1 J4.4 J5.1 J5.2 J5.3 J5.4 R1.2 R3.2 SB3.1 U2.2 | length 7.9
  Top Layer w0.152: R3.2 v1(20,18.1)
  Bottom Layer w0.152: v1(20,18.1) 20,22.746 20.754,23.5 J5.1
  other v1: 47.079,16.565 46.579,17.565 45.079,18.565 46.079,18.565 47.079,18.565 48.079,18.565 44.579,19.565 43.079,20.565 43.579,21.565 42.079,22.565 43.079,22.565 31.584,23.55 32.584,23.55 33.584,23.55 34.585,23.55 35.585,23.55 36.585,23.55 37.585,23.55 38.579,23.565 39.579,23.565 40.579,23.565 41.579,23.565 42.579,23.565 43.579,23.565
Vdd_MA: C6.1 Cd1.1 J1.1 U4.1 | length 10.1
  Top Layer w0.254: Cd1.1@4.5,13.026 4.776,13.026 5.303,12.5 U4.1 ; U4.1@6.15,12.502 6.15,13.521 C6.1@6.2,13.571
  Top Layer w0.381: J1.1 1.592,17.888 3.322,17.888 4.5,16.709 Cd1.1@4.5,13.026
VIN: C1.1 C2.1 SB3.2 SB4.2 U3.3 | length 4.2
  Top Layer w0.381: U3.3 14.1,3.975 14.746,4.621 C1.1 17.757,4.621 C2.1@17.779,4.6
Viso_MA: J1.5 X1.2 | length 6.9
  Top Layer w0.762: J1.5 5.036,7.82 6.225,6.631 X1.2
Viso_SM: R4.2 SB4.1 X1.4 | length 1.9
  Top Layer w0.381: R4.2@10.426,6.472 10.426,5.887 11.305,5.008 X1.4
pads on no net: J0. J0.6 ST1.1 ST2.1 ST3.1 U1.28

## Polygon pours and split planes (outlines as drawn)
OUT2_1 on GND1 "OUT2_1_L02_P148" (solid, remove dead copper, pour order 148): 34.8,21.9 34.3,21.4 34.3,18.5 30.65,14.85 24.65,14.85 23.7,13.9 23.7,13.2 23.9,13 33.75,13 37.2,16.45 37.2,21.3 36.6,21.9
OUT1_1 on GND1 "OUT1_1_L02_P197" (solid, remove dead copper, pour order 197): 34.8,3.1 34.3,3.6 34.3,6.5 30.65,10.15 24.65,10.15 23.7,11.1 23.7,11.8 23.9,12 33.75,12 37.2,8.55 37.2,3.7 36.6,3.1
GND_SM on GND1 "GND1-GND_SM" (solid, remove dead copper, pour order 208): 8.1,0 8.1,25 39.3,25 39.3,0
GND_SM on GND1 "Top Layer-VCAP_SM" (solid, remove dead copper, pour order 198): 33.778,2.5 34.178,2.1 38.11,2.1 38.91,2.9 41.2,2.9 42.2,3.9 42.2,5.2 46.7,9.7 50,9.7 50,0 21,0 21,2.5
OUT1_2 on GND1 "NONET_L-01_P-001" (solid, remove dead copper, pour order 200): 41.1,3.1 42,4 42,5.3 46.7,10 50,10 50,12.3 39.5,12.3 39.5,3.1
OUT2_2 on GND1 "NONET_L-01_P-001" (solid, remove dead copper, pour order 206): 41.1,21.9 42,21 42,19.7 46.7,15 50,15 50,12.7 39.5,12.7 39.5,21.9
VCAP_SM on GND1 "Top Layer-VCAP_SM" (solid, remove dead copper, pour order 202): 32.9,22.5 33.3,22.9 38.9,22.9 39.7,22.1 41.2,22.1 42.2,21.1 42.2,19.8 46.7,15.3 50,15.3 50,25 20,25 20,22.5
GND_MA on GND1 "L2_GND_MA" (solid, remove dead copper, pour order 207): 0,2 0,27.5 6.9,27.5 6.9,2
OUT2_1 on GND2 "OUT2_1_L03_P101" (solid, remove dead copper, pour order 101): 34.8,21.9 34.3,21.4 34.3,18.5 30.65,14.85 24.65,14.85 23.7,13.9 23.7,13.2 23.9,13 33.75,13 37.2,16.45 37.2,21.3 36.6,21.9
OUT1_1 on GND2 "OUT1_1_L03_P164" (solid, remove dead copper, pour order 164): 34.8,3.1 34.3,3.6 34.3,6.5 30.65,10.15 24.65,10.15 23.7,11.1 23.7,11.8 23.9,12 33.75,12 37.2,8.55 37.2,3.7 36.6,3.1
GND_SM on GND2 "Top Layer-VCAP_SM" (solid, remove dead copper, pour order 213): 33.778,2.5 34.178,2.1 38.376,2.1 39.176,2.9 41.2,2.9 42.2,3.9 42.2,5.2 46.7,9.7 50,9.7 50,0 21,0 21,2.5
OUT1_2 on GND2 "NONET_L-01_P-001" (solid, remove dead copper, pour order 214): 41.1,3.1 42,4 42,5.3 46.7,10 50,10 50,12.3 39.5,12.3 39.5,3.1
VCAP_SM on GND2 "Top Layer-VCAP_SM" (solid, remove dead copper, pour order 181): 32.8,22.5 33.2,22.9 38.9,22.9 39.7,22.1 41.2,22.1 42.2,21.1 42.2,19.8 46.7,15.3 50,15.3 50,25 20,25 20,22.5
OUT2_2 on GND2 "NONET_L-01_P-001" (solid, remove dead copper, pour order 212): 41.1,21.9 42,21 42,19.7 46.7,15 50,15 50,12.7 39.5,12.7 39.5,21.9
GND_SM on GND2 "GND1-GND_SM" (solid, remove dead copper, pour order 236): 8.1,0 8.1,25 39.3,25 39.3,0
GND_MA on GND2 "L3_GND_MA" (solid, remove dead copper, pour order 235): 0,2 0,27.5 6.9,27.5 6.9,2
Viso_SM on Top Layer "NONET_L-01_P-001" (solid, remove dead copper, pour order 146): 10.849,6 10,5.151 10,0.357 12.3,0.357 12.3,5.361 11.661,6
VIN on Top Layer "Top Layer-VIN" (solid, remove dead copper, pour order 132): 17.7,0.357 17.7,2.853 16.065,2.853 15.72,3.197 15.72,4.918 14.1,4.916 12.48,4.918 12.48,3.197 12.135,2.853 10.5,2.853 10.5,0.357
Cf1 on Top Layer "NONET_L-01_P-001" (solid, remove dead copper, pour order 156): 38.3,8.75 39.5,8.75 41.25,10.5 41.25,11 39.85,12.4 38.3,12.4
Cf2 on Top Layer "NONET_L-01_P-001" (solid, remove dead copper, pour order 160): 38.3,16.25 39.5,16.25 41.25,14.5 41.25,14 39.85,12.6 38.3,12.6
GND_SM on Top Layer "Top Layer-GND_SM" (solid, remove dead copper, pour order 243): 20.6,9 22.7,6.9 25.6,6.9 25.6,10.3 25.6,10.396 24.149,10.396 23.6,10.945 23.6,11.776 24.152,12.329 26.34,12.329 26.34,12.671 24.152,12.671 23.6,13.224 23.6,14.055 24.149,14.604 25.6,14.604 25.6,14.7 25.6,18.1 22.7,18.1 20.6,16
OUT1_1 on Top Layer "Top Layer-OUT1_1" (solid, remove dead copper, pour order 241): 28.965,12.125 29.4,11.69 29.4,11 29,10.6 27.89,10.6 27.79,10.7 27.79,11.6 27.615,11.775 25.565,11.775 25.39,11.6 25.39,10.7 25.29,10.6 24.18,10.6 23.78,11 23.78,11.69 24.215,12.125
OUT2_1 on Top Layer "Top Layer-OUT2_1" (solid, remove dead copper, pour order 240): 28.965,12.875 29.4,13.31 29.4,14 29,14.4 27.89,14.4 27.79,14.3 27.79,13.4 27.615,13.225 25.565,13.225 25.39,13.4 25.39,14.3 25.29,14.4 24.18,14.4 23.78,14 23.78,13.31 24.215,12.875
GND_SM on Top Layer "Top Layer-GND_SM 1" (solid, remove dead copper, pour order 238): 34.3,2.75 39.25,2.75 39.25,22 34.3,22
OUT1_1 on Top Layer "OUT1_1_L01_P165" (solid, remove dead copper, pour order 165): 34.8,3.1 34.3,3.6 34.3,11.45 37.2,8.55 37.2,3.7 36.6,3.1
OUT2_1 on Top Layer "OUT2_1_L01_P211" (solid, remove dead copper, pour order 211): 34.8,21.9 34.3,21.4 34.3,13.55 37.2,16.45 37.2,21.3 36.6,21.9
VCAP_SM on Top Layer "Top Layer-VCAP_SM" (solid, remove dead copper, pour order 219): 21,22.1 41.2,22.1 42.2,21.1 42.2,19.8 46.7,15.3 50,15.3 50,25 21,25
OUT2_2 on Top Layer "NONET_L-01_P-001" (solid, remove dead copper, pour order 225): 41.1,21.9 42,21 42,19.7 46.7,15 50,15 50,12.7 39.5,12.7 39.5,21.9
GND_SM on Top Layer "Top Layer-VCAP_SM" (solid, remove dead copper, pour order 228): 19.636,0 50,0 50,9.7 46.7,9.7 42.2,5.2 42.2,3.9 41.2,2.9 19.636,2.9
OUT1_2 on Top Layer "NONET_L-01_P-001" (solid, remove dead copper, pour order 229): 41.1,3.1 42,4 42,5.3 46.7,10 50,10 50,12.3 39.5,12.3 39.5,3.1
+3.3V_SM on Top Layer "+3.3V_SM_L01_P231" (solid, remove dead copper, pour order 231): 10.947,7.547 10.947,5.123 13.95,5.123 13.95,10.919 13.625,10.919 13.625,10.225
GND_SM on Top Layer "GND_SM_L01_P237" (solid, remove dead copper, pour order 237): 14.598,10.702 19.3,6 19.3,5.1 14.15,5.1 14.15,10.925 14.598,10.925
VCAP_SM on Top Layer "Top Layer-VCAP_SM 1" (solid, remove dead copper, pour order 239): 16.335,0 35.226,0 35.226,25 19.7,25 19.7,20.6 25.68,20.6 27.46,18.821 27.46,14.74 27.596,14.604 29.096,14.604 29.6,14.1 29.6,13.244 29.031,12.675 26.84,12.675 26.84,12.325 29.031,12.325 29.6,11.756 29.6,10.912 29.084,10.396 27.596,10.396 27.46,10.26 27.46,6.245 25.215,4 16.335,4
OUT2_1 on Bottom Layer "OUT2_1_L04_P215" (solid, remove dead copper, pour order 215): 34.8,21.9 34.3,21.4 34.3,18.5 30.65,14.85 24.65,14.85 23.7,13.9 23.7,13.2 23.9,13 33.75,13 37.2,16.45 37.2,21.3 36.6,21.9
OUT1_1 on Bottom Layer "OUT1_1_L04_P201" (solid, remove dead copper, pour order 201): 34.8,3.1 34.3,3.6 34.3,6.5 30.65,10.15 24.65,10.15 23.7,11.1 23.7,11.8 23.9,12 33.75,12 37.2,8.55 37.2,3.7 36.6,3.1
GND_SM on Bottom Layer "GND1-GND_SM" (solid, remove dead copper, pour order 234): 21,0 39.3,0 39.3,25 21,25
GND_SM on Bottom Layer "Top Layer-VCAP_SM" (solid, remove dead copper, pour order 232): 33.778,2.5 34.178,2.1 38.11,2.1 38.91,2.9 41.2,2.9 42.2,3.9 42.2,5.2 46.7,9.7 50,9.7 50,0 21,0 21,2.5
OUT1_2 on Bottom Layer "NONET_L-01_P-001" (solid, remove dead copper, pour order 233): 41.1,3.1 42,4 42,5.3 46.7,10 50,10 50,12.3 39.5,12.3 39.5,3.1
VCAP_SM on Bottom Layer "Top Layer-VCAP_SM" (solid, remove dead copper, pour order 217): 33.778,22.5 34.178,22.9 38.9,22.9 39.7,22.1 41.2,22.1 42.2,21.1 42.2,19.8 46.7,15.3 50,15.3 50,25 19.8,25 19.8,22.5
OUT2_2 on Bottom Layer "NONET_L-01_P-001" (solid, remove dead copper, pour order 218): 41.1,21.9 42,21 42,19.7 46.7,15 50,15 50,12.7 39.5,12.7 39.5,21.9

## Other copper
Top Layer:
  text "1" at 2.731,0.492 h1.02
GND1:
  text "2" at 3.561,0.492 h1.02
GND2:
  text "3" at 4.661,0.492 h1.02
Bottom Layer:
  text "4" at 5.661,0.492 h1.02
Multi-Layer:
  pour cut-out: 6.9,3.327 6.9,25 8.1,25 8.1,3.327 7.95,3.177 7.95,2.177 8.1,2.027 8.1,0 6.9,0 6.9,2.027 7.05,2.177 7.05,3.177

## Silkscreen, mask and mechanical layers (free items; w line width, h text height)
Top Overlay:
  drawing of 118 lines, arcs and shapes, not listed
  text "STAT" at 17.988,23.8 h1
  text "COM" at 17.988,22.391 h1
  text "https://github.com/ / mmcmerlin/Micro-MMC" at 32.532,22.2 h1.1
  text "sync2" at 16.249,21.754 h1 r270
  text "SM+ / VCAP" at 20.941,20.574 h1.52
  text "Lf" at 37.144,20.5 h1
  text "EN2" at 23.544,19.5 h1
  text "sync1" at 16.249,19.17 h1 r270
  text "PWM2" at 21.588,18.5 h1
  text "reset" at 9.388,18.249 h1 r90
  text "DC: 4-14V, 0-5A" at 42.11,18.023 h1.5 r270
  text "VDD" at 2.957,17.898 h1
  text "Csm" at 25.544,16.9 h1
  text "3V3" at 2.957,16.698 h1
  text "Cf" at 37.144,16.7 h1
  text "Cf Solder Bridge" at 35.553,15.921 h1 r270
  text "VCAP" at 43.7,15.427 h1.52
  text "ISOLATION" at 8,15 h1.2 r90
  text "Csm" at 31.726,13.556 h1 r270
  text "CM2" at 20.555,13.295 h1
  text "TX" at 7.9,12.888 h1 r90
  text "OUT2" at 43.7,12.887 h1.52
  text "CM1" at 20.555,10.895 h1
  text "OUT1" at 43.7,10.347 h1.52
  text "PTP" at 9.826,7.95 h1
  text "GND" at 43.7,7.807 h1.52
  text "Viso" at 2.857,7.698 h1
  text "Cf" at 37.144,7.5 h1
  text "nFLT" at 21.088,7.3 h1
  text "Csm" at 25.544,7.3 h1
  text "RX" at 7.9,7.288 h1 r90
  text "3V3" at 12.563,6.7 h1
  text "5V0" at 2.857,6.498 h1
  text "PWM1" at 21.588,5.7 h1
  text "X" at 29.368,5.139 h7
  text "EN1" at 23.577,4.614 h1
  text "Lf" at 37.144,3.7 h1
  text "SM- / GND" at 21.027,2.712 h1.52
  text "layers" at 2.8,1.8 h1
  text "Power Select" at 12.8,1.3 h1
  text "Viso / ext" at 7.95,0.1 h1
  text "bridge" at 12.5,0.1 h1
  text "Vsm / cap" at 18.55,0.1 h1
Bottom Overlay:
  drawing of 55 lines, arcs and shapes, not listed
  text "SM+ / VCAP" at 31.341,20.574 h1.52
  text "sync2" at 16.599,19.356 h1 r270
  text "VDD" at 5.243,17.898 h1
  text "ISOLATION" at 8,17.5 h1.2 r90
  text "sync1" at 16.599,16.77 h1 r270
  text "Timers" at 17.545,16.77 h1 r270
  text "3V3" at 5.243,16.698 h1
  text "VCAP" at 47.079,15.427 h1.52
  text "TX" at 5.143,14.686 h1
  text "ver3.40" at 15.5,14.1 h1.5
  text "06/2025" at 22,14.1 h1.5
  text "OUT2" at 47.079,12.887 h1.52
  text "GND" at 5.143,12.198 h1
  text "OUT1" at 47.079,10.347 h1.52
  text "Micro-MMC Sub-Module" at 22,10.1 h2
  text "RX" at 5.143,9.586 h1
  text "MMC Merlin" at 22,8.564 h1.5
  text "GND" at 47.079,7.807 h1.52
  text "Viso" at 5.143,7.698 h1
  text "5V0" at 5.143,6.498 h1
  text "SM- / GND" at 31.427,2.712 h1.52
  text "O" at 20.512,-1.707 h13
Top Solder:
  rectangle: 2.465,0.2 6.6,1.8
Bottom Solder:
  rectangle: 2.465,0.2 6.6,1.8
Board:
  the board outline again, w0.254
Dimensions:
  region: 21,0 21,2.8 31.5,2.8 31.5,22.25 21,22.25 21,25 5.7,25 5.7,6.5 13.7,6.5 13.7,0
  lines w0.254: 5.7,0 31.7,0 31.7,25 5.7,25 5.7,0
  lines w0.3: 24.92,1.5 24.92,23.5 ; 27.46,1.5 27.46,23.5 ; 22.38,1.5 30,1.5 30,23.5 22.38,23.5 22.38,1.5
